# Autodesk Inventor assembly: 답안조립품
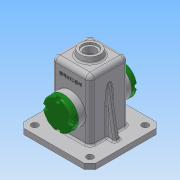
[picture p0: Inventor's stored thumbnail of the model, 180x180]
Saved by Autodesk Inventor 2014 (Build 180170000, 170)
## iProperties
Created: 2016-02
Part Number: 답안조립품
Document SubType Name: Assembly
Designer: User
Author: User
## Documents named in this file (4)
- C:\Documents and Settings\User\My Documents\Inventor\460211V1024\답안조립품.iam
- C:\Documents and Settings\User\My Documents\Inventor\460211V1024\본체.ipt
- C:\Documents and Settings\User\My Documents\Inventor\460211V1024\앞커버.ipt
- C:\Documents and Settings\User\My Documents\Inventor\460211V1024\뒤커버.ipt
